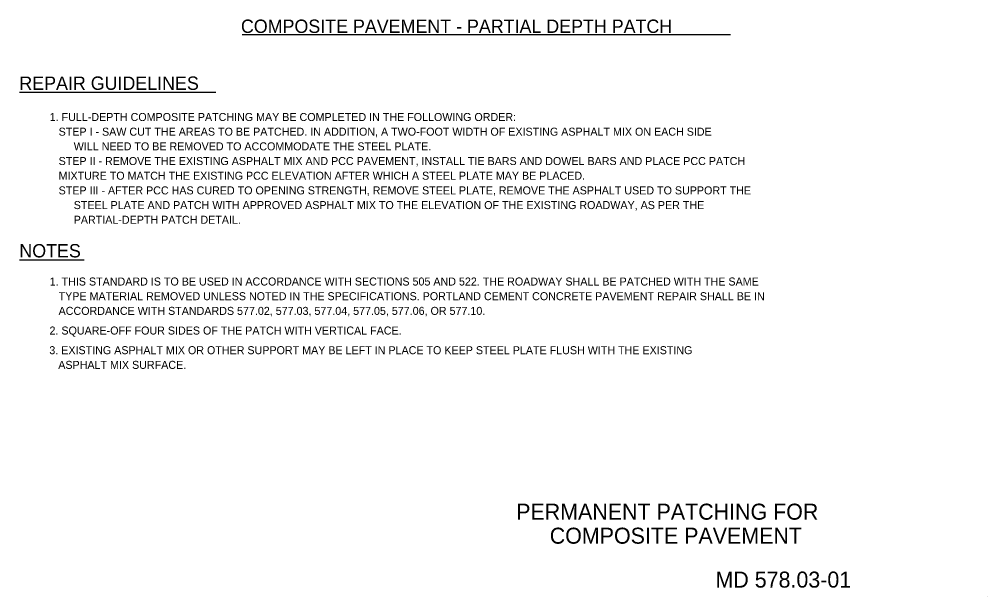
# Model space of a CAD drawing. Extents: x 3.47 to 10.73, y 1.11 to 10.92.
# Drawn here: x 3.47 to 10.73, y 1.11 to 5.44 of the extents above; entities that cross this region are included whole.
import ezdxf

# ---------------------------------------------------------------- set-up
doc = ezdxf.new("R2010")
doc.units = 0
for name, color, linetype in [('DETL-NOTE', 7, 'Continuous'), ('DETL-TITL', 7, 'Continuous'), ('TTLB-TEXT', 7, 'Continuous')]:
    doc.layers.add(name, color=color, linetype=linetype)

msp = doc.modelspace()

# ---------------------------------------------------------------- linework, layer by layer
at = {"layer": 'DETL-NOTE'}
for p, q in [((5.142, 5.3265), (8.8013, 5.3265)), ((3.4712, 4.8953), (4.9447, 4.8953)), ((3.4712, 3.6396), (3.9573, 3.6396))]:
    msp.add_line(p, q, dxfattribs=at)
at = {"layer": 'TTLB-TEXT'}
msp.add_line((10.7278, 1.1148), (10.7278, 1.1148), dxfattribs=at)

# ---------------------------------------------------------------- texts
at = {"layer": 'DETL-NOTE'}
for s, height, p in [('REPAIR GUIDELINES', 0.1, (3.4712, 4.9123)), ('1. FULL-DEPTH COMPOSITE PATCHING MAY BE COMPLETED IN THE FOLLOWING ORDER:', 0.06, (3.6985, 4.6789)), ('   STEP I - SAW CUT THE AREAS TO BE PATCHED. IN ADDITION, A TWO-FOOT WIDTH OF EXISTING ASPHALT MIX ON EACH SIDE ', 0.06, (3.6985, 4.5689)), ('WILL NEED TO BE REMOVED TO ACCOMMODATE THE STEEL PLATE.', 0.06, (3.8785, 4.4589)), ('   STEP II - REMOVE THE EXISTING ASPHALT MIX AND PCC PAVEMENT, INSTALL TIE BARS AND DOWEL BARS AND PLACE PCC PATCH ', 0.06, (3.6985, 4.3489)), ('   MIXTURE TO MATCH THE EXISTING PCC ELEVATION AFTER WHICH A STEEL PLATE MAY BE PLACED.', 0.06, (3.6985, 4.2389)), ('   STEP III - AFTER PCC HAS CURED TO OPENING STRENGTH, REMOVE STEEL PLATE, REMOVE THE ASPHALT USED TO SUPPORT THE ', 0.06, (3.6985, 4.1289)), ('STEEL PLATE AND PATCH WITH APPROVED ASPHALT MIX TO THE ELEVATION OF THE EXISTING ROADWAY, AS PER THE ', 0.06, (3.8785, 4.0189)), ('PARTIAL-DEPTH PATCH DETAIL.', 0.06, (3.8785, 3.9089)), ('NOTES', 0.1, (3.4712, 3.6567)), ('1. THIS STANDARD IS TO BE USED IN ACCORDANCE WITH SECTIONS 505 AND 522. THE ROADWAY SHALL BE PATCHED WITH THE SAME', 0.06, (3.6985, 3.4461)), ('   TYPE MATERIAL REMOVED UNLESS NOTED IN THE SPECIFICATIONS. PORTLAND CEMENT CONCRETE PAVEMENT REPAIR SHALL BE IN', 0.06, (3.6985, 3.3361)), ('   ACCORDANCE WITH STANDARDS 577.02, 577.03, 577.04, 577.05, 577.06, OR 577.10.', 0.06, (3.6985, 3.2261)), ('2. SQUARE-OFF FOUR SIDES OF THE PATCH WITH VERTICAL FACE.', 0.06, (3.6972, 3.0788)), ('3. EXISTING ASPHALT MIX OR OTHER SUPPORT MAY BE LEFT IN PLACE TO KEEP STEEL PLATE FLUSH WITH THE EXISTING', 0.06, (3.6959, 2.9315)), ('   ASPHALT MIX SURFACE.', 0.06, (3.6959, 2.8215))]:
    msp.add_text(s, height=height, dxfattribs=at).set_placement(p)
at = {"layer": 'DETL-TITL'}
msp.add_text('COMPOSITE PAVEMENT - PARTIAL DEPTH PATCH', height=0.1, dxfattribs=at).set_placement((5.1318, 5.339))
at = {"layer": 'TTLB-TEXT'}
for s, p in [('PERMANENT PATCHING FOR', (7.1945, 1.6914)), ('COMPOSITE PAVEMENT', (7.4461, 1.5114)), ('MD 578.03-01', (8.6883, 1.1824))]:
    msp.add_text(s, height=0.12, dxfattribs=at).set_placement(p)

doc.saveas('drawing.dxf')
